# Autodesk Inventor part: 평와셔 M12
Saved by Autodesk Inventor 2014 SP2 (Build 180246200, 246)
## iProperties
Created: 2024-04
Part Number: 평와셔 M12
Material: Generic
Document SubType Name: Modeling
Designer: Administrator
Density: 1 g/cm^3
Appearance: Default
Author: Administrator
Author: jhkim
Description: 평면 와셔
Creation Date: 2024-04-08
Sending System: Autodesk Inventor 2025
Preprocessor: ST-DEVELOPER v20
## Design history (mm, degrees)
node "평와셔 M121"
body "Solid1"
node "기준1"
